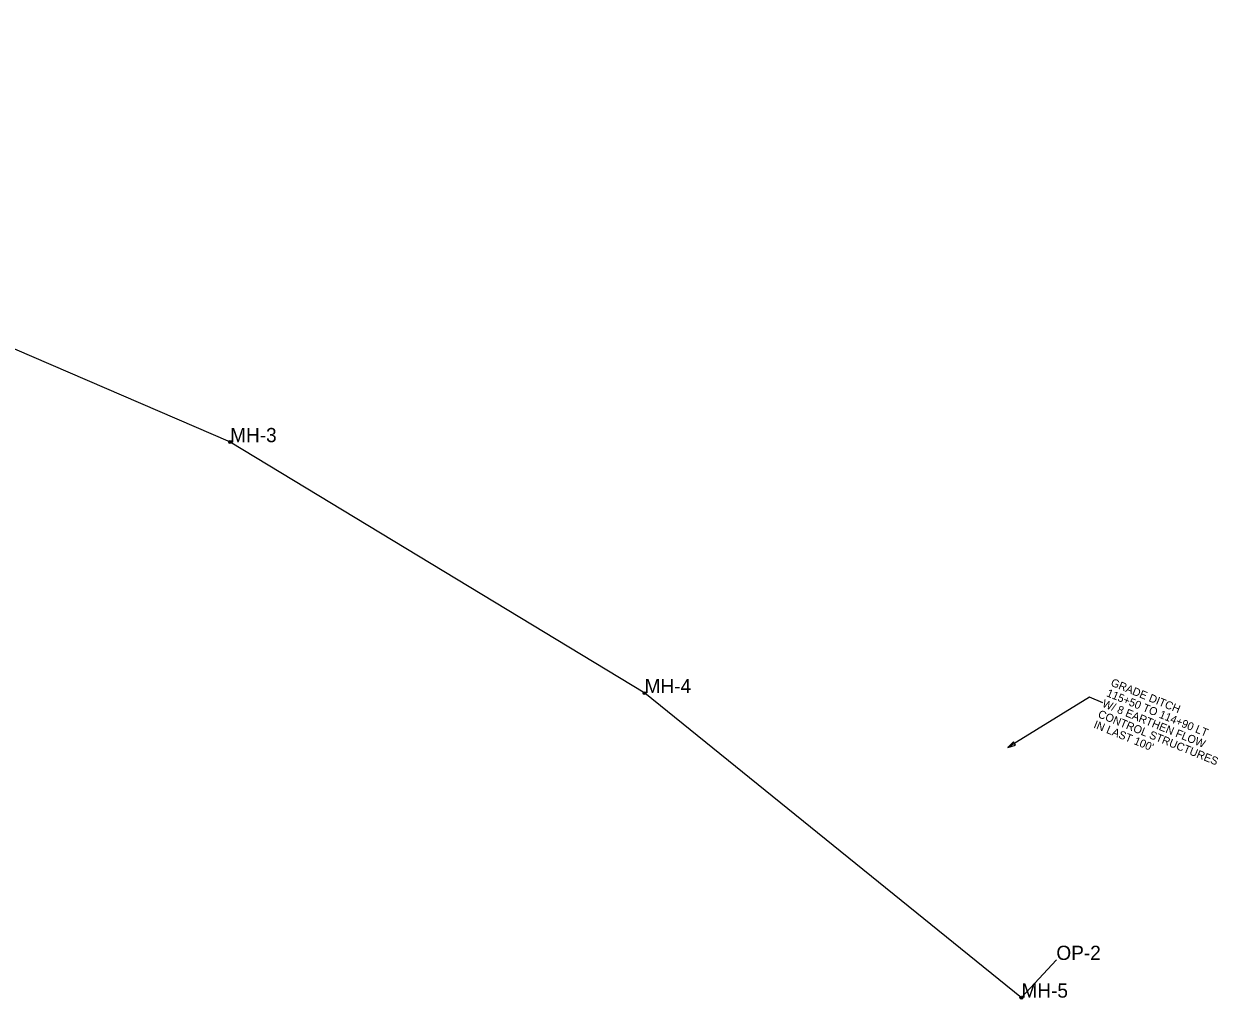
# Model space of a CAD drawing. Extents: x 2165744 to 2171481, y 206867 to 209489.
# Drawn here: x 2170810 to 2171481, y 206867 to 207415 of the extents above; entities that cross this region are included whole.
import ezdxf

# ---------------------------------------------------------------- set-up
doc = ezdxf.new("R2010")
doc.units = 0
for name, color, linetype in [('RD_PD_DR_Inlet', 7, 'Continuous'), ('RD_PD_DR_Inlet_TX', 7, 'Continuous'), ('RD_PD_DR_Pipe', 7, 'Continuous'), ('RD_TX_Drainage', 7, 'Continuous')]:
    doc.layers.add(name, color=color, linetype=linetype)

msp = doc.modelspace()

# ---------------------------------------------------------------- linework, layer by layer
at = {"layer": 'RD_PD_DR_Inlet'}
for p, q in [((2170924.98, 207180.1), (2170924.98, 207180.1)), ((2170925.25, 207179.28), (2170925.25, 207179.28)), ((2170925.25, 207179.28), (2170925.25, 207179.28)), ((2170925.53, 207179.82), (2170925.53, 207179.82)), ((2170925.53, 207179.82), (2170925.53, 207179.82)), ((2170925.81, 207180.36), (2170925.81, 207180.36)), ((2170925.81, 207180.36), (2170925.81, 207180.36)), ((2170926.07, 207179.54), (2170926.07, 207179.54)), ((2171157.94, 207039), (2171157.94, 207039)), ((2171158.09, 207038.15), (2171158.09, 207038.15)), ((2171158.09, 207038.15), (2171158.09, 207038.15)), ((2171158.44, 207038.65), (2171158.44, 207038.65)), ((2171158.44, 207038.65), (2171158.44, 207038.65)), ((2171158.79, 207039.15), (2171158.79, 207039.15)), ((2171158.79, 207039.15), (2171158.79, 207039.15)), ((2171158.94, 207038.29), (2171158.94, 207038.29)), ((2171369.84, 206867.89), (2171369.84, 206867.89)), ((2171369.87, 206867.02), (2171369.87, 206867.02)), ((2171369.87, 206867.02), (2171369.87, 206867.02)), ((2171370.28, 206867.47), (2171370.28, 206867.47)), ((2171370.28, 206867.47), (2171370.28, 206867.47)), ((2171370.7, 206867.92), (2171370.7, 206867.92)), ((2171370.7, 206867.92), (2171370.7, 206867.92)), ((2171370.73, 206867.06), (2171370.73, 206867.06))]:
    msp.add_line(p, q, dxfattribs=at)
for centre, radius in [((2170925.53, 207179.82), 0.833), ((2170925.53, 207179.82), 0.611), ((2171158.44, 207038.65), 0.833), ((2171158.44, 207038.65), 0.611), ((2171370.28, 206867.47), 0.833), ((2171370.28, 206867.47), 0.611)]:
    msp.add_circle(centre, radius, dxfattribs=at)
at = {"layer": 'RD_PD_DR_Pipe'}
for p, q in [((2170380.45, 207414.91), (2170925.55, 207179.85)), ((2170925.55, 207179.85), (2171158.51, 207038.75)), ((2171158.51, 207038.75), (2171370.37, 206867.56)), ((2171370.37, 206867.56), (2171389.91, 206888.66))]:
    msp.add_line(p, q, dxfattribs=at)
at = {"layer": 'RD_TX_Drainage'}
msp.add_lwpolyline([(2171416.11, 207033.23), (2171408.54, 207036.31), (2171362.71, 207008.04)], dxfattribs=at)
msp.add_lwpolyline([(2171365.79, 207011.32), (2171362.71, 207008.04), (2171367.02, 207009.33)], close=True, dxfattribs=at)

# ---------------------------------------------------------------- texts
at = {"layer": 'RD_PD_DR_Inlet'}
msp.add_text('OP', height=0.001, rotation=139.83193, dxfattribs=at).set_placement((2171389.91, 206888.66))
at = {"layer": 'RD_PD_DR_Inlet_TX'}
for s, p in [('MH-3', (2170925.48, 207179.75)), ('MH-4', (2171158.44, 207038.65)), ('OP-2', (2171389.91, 206888.66)), ('MH-5', (2171370.28, 206867.47))]:
    msp.add_text(s, height=8, dxfattribs=at).set_placement(p)
at = {"layer": 'RD_TX_Drainage'}
for s, p in [('GRADE DITCH', (2171420.1, 207042.94)), ('115+50 TO 114+90 LT', (2171417.7, 207037.03)), ('W/ 8 EARTHEN FLOW', (2171415.29, 207031.13)), ('CONTROL STRUCTURES', (2171412.89, 207025.23)), ("IN LAST 100'", (2171410.48, 207019.32))]:
    msp.add_text(s, height=4.5, rotation=337.83882, dxfattribs=at).set_placement(p)

doc.saveas('drawing.dxf')
